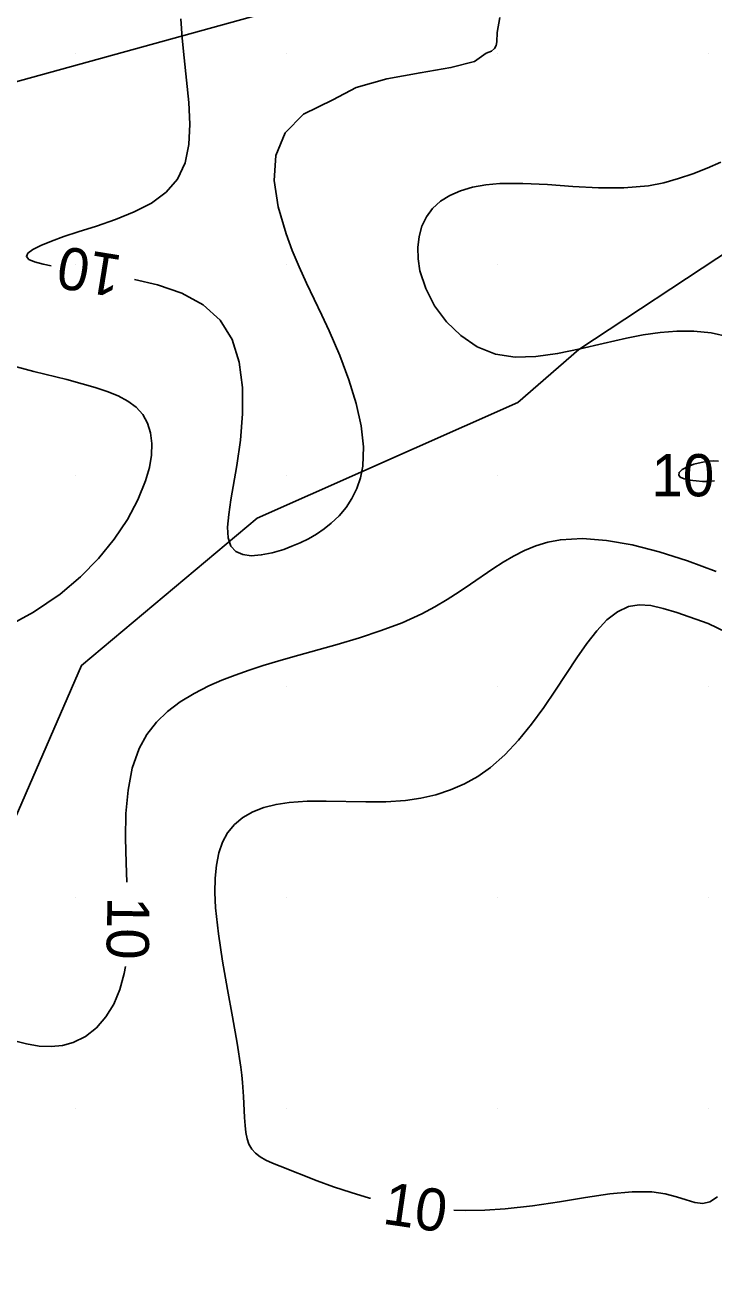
# Model space of a CAD drawing. Extents: x 2602990 to 2605851, y 618069 to 619180.
# Drawn here: x 2603247.6 to 2603280.3, y 618261.9 to 618321.3 of the extents above; entities that cross this region are included whole.
import ezdxf

# ---------------------------------------------------------------- set-up
doc = ezdxf.new("R2010")
doc.units = 0
for name, color, linetype in [('DTM Contours Major', 7, 'Continuous'), ('DTM Contours Major Text', 7, 'Continuous'), ('DTM Contours Minor', 7, 'Continuous'), ('DTM Contours Minor Text', 7, 'Continuous'), ('Exist DTM QL2 LIDAR Elevation Point', 7, 'Continuous'), ('PH Exist DTM Obscure Area', 7, 'Continuous')]:
    doc.layers.add(name, color=color, linetype=linetype)

msp = doc.modelspace()

# ---------------------------------------------------------------- linework, layer by layer
at = {"layer": 'DTM Contours Major'}
for points in [[(2603280.976, 618306.565), (2603280.141, 618306.74), (2603279.32, 618306.823), (2603278.511, 618306.827), (2603277.711, 618306.765), (2603276.916, 618306.651), (2603276.126, 618306.498), (2603275.02, 618306.246), (2603273.928, 618305.988), (2603272.86, 618305.765), (2603271.828, 618305.622), (2603270.844, 618305.601), (2603269.918, 618305.744), (2603269.048, 618306.09), (2603268.266, 618306.613), (2603267.589, 618307.272), (2603267.032, 618308.031), (2603266.609, 618308.848), (2603266.337, 618309.686), (2603266.245, 618310.251), (2603266.229, 618310.798), (2603266.291, 618311.32), (2603266.429, 618311.807), (2603266.644, 618312.251), (2603266.935, 618312.643), (2603267.307, 618312.981), (2603267.75, 618313.26), (2603268.26, 618313.481), (2603268.829, 618313.646), (2603269.451, 618313.759), (2603270.121, 618313.821), (2603271.216, 618313.83), (2603272.378, 618313.771), (2603273.582, 618313.687), (2603274.798, 618313.622), (2603276.001, 618313.618), (2603277.162, 618313.72), (2603277.89, 618313.861), (2603278.592, 618314.054), (2603279.273, 618314.289), (2603279.937, 618314.555), (2603280.588, 618314.84)], [(2603247.219, 618305.132), (2603248.043, 618304.919), (2603249.604, 618304.529), (2603250.331, 618304.338), (2603250.945, 618304.161), (2603251.516, 618303.97), (2603252.036, 618303.756), (2603252.495, 618303.508), (2603252.886, 618303.218), (2603253.199, 618302.876), (2603253.429, 618302.474), (2603253.574, 618302.016), (2603253.635, 618301.507), (2603253.615, 618300.952), (2603253.515, 618300.358), (2603253.336, 618299.729), (2603252.972, 618298.833), (2603252.473, 618297.907), (2603251.848, 618296.974), (2603251.103, 618296.058), (2603250.245, 618295.181), (2603249.281, 618294.368), (2603248.03, 618293.517), (2603246.696, 618292.78)], [(2603252.447, 618280.716), (2603252.409, 618281.629), (2603252.383, 618282.806), (2603252.406, 618283.966), (2603252.504, 618285.079), (2603252.704, 618286.118), (2603253.032, 618287.054), (2603253.398, 618287.711), (2603253.851, 618288.292), (2603254.382, 618288.806), (2603254.979, 618289.259), (2603255.632, 618289.66), (2603256.331, 618290.017), (2603256.944, 618290.285), (2603257.579, 618290.532), (2603258.236, 618290.762), (2603258.912, 618290.977), (2603259.605, 618291.184), (2603260.314, 618291.386), (2603262.42, 618291.976), (2603263.473, 618292.292), (2603264.503, 618292.634), (2603265.491, 618293.011), (2603266.422, 618293.432), (2603267.041, 618293.763), (2603267.629, 618294.113), (2603268.191, 618294.475), (2603268.734, 618294.842), (2603269.788, 618295.562), (2603270.278, 618295.878), (2603270.776, 618296.17), (2603271.289, 618296.431), (2603271.825, 618296.652), (2603272.391, 618296.825), (2603272.995, 618296.942), (2603274.035, 618296.999), (2603275.171, 618296.912), (2603276.389, 618296.697), (2603277.673, 618296.369), (2603279.007, 618295.946), (2603280.375, 618295.442)], [(2603247.067, 618273.212), (2603247.695, 618273.048), (2603248.295, 618272.951), (2603248.867, 618272.927), (2603249.405, 618272.979), (2603249.907, 618273.111), (2603250.491, 618273.399), (2603251.008, 618273.809), (2603251.454, 618274.327), (2603251.824, 618274.939), (2603252.115, 618275.63), (2603252.324, 618276.386), (2603252.38, 618276.725)]]:
    msp.add_lwpolyline(points, dxfattribs=at)
at = {"layer": 'DTM Contours Minor'}
for points in [[(2603269.479, 618320), (2603269.72, 618320.094), (2603269.868, 618320.216), (2603269.947, 618320.366), (2603269.979, 618320.544), (2603270, 618320.984), (2603270.122, 618321.689)], [(2603255.009, 618321.62), (2603255.064, 618320.713), (2603255.156, 618319.782), (2603255.279, 618318.716), (2603255.386, 618317.66), (2603255.437, 618316.639), (2603255.391, 618315.678), (2603255.21, 618314.803), (2603254.853, 618314.037), (2603254.311, 618313.414), (2603253.61, 618312.899), (2603252.795, 618312.474), (2603251.915, 618312.117), (2603251.015, 618311.809), (2603250.142, 618311.529), (2603249.469, 618311.305), (2603248.871, 618311.09), (2603248.371, 618310.885), (2603247.992, 618310.693), (2603247.758, 618310.516), (2603247.693, 618310.357), (2603247.804, 618310.224), (2603248.071, 618310.104), (2603248.478, 618309.995), (2603248.866, 618309.919)], [(2603252.815, 618309.282), (2603253.903, 618309.021), (2603255.046, 618308.62), (2603256.059, 618308.075), (2603256.872, 618307.353), (2603257.437, 618306.431), (2603257.775, 618305.35), (2603257.926, 618304.16), (2603257.929, 618302.914), (2603257.827, 618301.663), (2603257.659, 618300.459), (2603257.38, 618298.836), (2603257.276, 618298.138), (2603257.225, 618297.532), (2603257.251, 618297.03), (2603257.376, 618296.643), (2603257.607, 618296.387), (2603257.936, 618296.239), (2603258.345, 618296.187), (2603258.817, 618296.22), (2603259.336, 618296.324), (2603259.883, 618296.487), (2603260.273, 618296.631), (2603260.665, 618296.799), (2603261.052, 618296.991), (2603261.429, 618297.209), (2603261.791, 618297.453), (2603262.133, 618297.723), (2603262.503, 618298.075), (2603262.832, 618298.466), (2603263.115, 618298.896), (2603263.345, 618299.365), (2603263.518, 618299.874), (2603263.626, 618300.424), (2603263.662, 618301.341), (2603263.552, 618302.338), (2603263.316, 618303.402), (2603262.971, 618304.516), (2603262.537, 618305.667), (2603262.032, 618306.838), (2603261.683, 618307.588), (2603260.964, 618309.101), (2603260.615, 618309.869), (2603260.286, 618310.646), (2603259.989, 618311.434), (2603259.612, 618312.711), (2603259.425, 618313.969), (2603259.509, 618315.158), (2603259.947, 618316.224), (2603260.822, 618317.117), (2603262.215, 618317.785), (2603263.317, 618318.38), (2603264.768, 618318.783), (2603266.34, 618319.071), (2603267.802, 618319.32), (2603268.924, 618319.604), (2603269.479, 618320)], [(2603278.604, 618300), (2603278.615, 618300.131), (2603278.761, 618300.268), (2603279.007, 618300.399), (2603279.318, 618300.517), (2603279.661, 618300.609), (2603280, 618300.667), (2603280.254, 618300.683), (2603280.482, 618300.673)], [(2603280.291, 618299.727), (2603280, 618299.704), (2603279.726, 618299.707), (2603279.418, 618299.73), (2603279.114, 618299.772), (2603278.851, 618299.832), (2603278.669, 618299.908), (2603278.604, 618300)], [(2603280, 618292.977), (2603278.503, 618293.49), (2603277.858, 618293.691), (2603277.27, 618293.822), (2603276.728, 618293.859), (2603276.222, 618293.778), (2603275.697, 618293.533), (2603275.197, 618293.141), (2603274.714, 618292.63), (2603274.244, 618292.024), (2603273.777, 618291.352), (2603272.766, 618289.815), (2603272.207, 618288.993), (2603271.624, 618288.195), (2603271.012, 618287.441), (2603270.365, 618286.751), (2603269.678, 618286.148), (2603269.074, 618285.725), (2603268.441, 618285.371), (2603267.78, 618285.085), (2603267.092, 618284.861), (2603266.38, 618284.696), (2603265.646, 618284.589), (2603264.714, 618284.525), (2603263.766, 618284.515), (2603261.889, 618284.553), (2603260.993, 618284.548), (2603260.146, 618284.494), (2603259.519, 618284.399), (2603258.939, 618284.251), (2603258.414, 618284.047), (2603257.948, 618283.783), (2603257.549, 618283.455), (2603257.222, 618283.059), (2603256.979, 618282.61), (2603256.803, 618282.099), (2603256.689, 618281.528), (2603256.629, 618280.903), (2603256.62, 618280.228), (2603256.654, 618279.506), (2603256.784, 618278.268), (2603256.982, 618276.964), (2603257.217, 618275.636), (2603257.461, 618274.329), (2603257.683, 618273.084), (2603257.854, 618271.944), (2603257.897, 618271.57), (2603257.931, 618271.215), (2603257.979, 618270.558), (2603258.027, 618269.559), (2603258.05, 618269.186), (2603258.087, 618268.851), (2603258.145, 618268.554), (2603258.234, 618268.293), (2603258.363, 618268.067), (2603258.541, 618267.871), (2603258.766, 618267.701), (2603259.038, 618267.547), (2603259.355, 618267.402), (2603259.714, 618267.255), (2603261.463, 618266.569), (2603262.239, 618266.284), (2603263.071, 618266.005), (2603263.953, 618265.747), (2603263.986, 618265.739)], [(2603280.843, 618292.559), (2603280, 618292.977)], [(2603267.936, 618265.166), (2603268.475, 618265.149), (2603269.416, 618265.165), (2603270.368, 618265.227), (2603271.664, 618265.376), (2603272.942, 618265.571), (2603274.176, 618265.773), (2603275.337, 618265.945), (2603276.396, 618266.047), (2603277.326, 618266.042), (2603277.947, 618265.949), (2603278.485, 618265.808), (2603278.955, 618265.658), (2603279.367, 618265.541), (2603279.737, 618265.494), (2603280.077, 618265.56), (2603280.438, 618265.801)]]:
    msp.add_lwpolyline(points, dxfattribs=at)
at = {"layer": 'Exist DTM QL2 LIDAR Elevation Point'}
for p, q in [((2603250, 618320), (2603250, 618320)), ((2603260, 618320), (2603260, 618320)), ((2603270, 618320), (2603270, 618320)), ((2603280, 618320), (2603280, 618320)), ((2603250, 618310), (2603250, 618310)), ((2603260, 618310), (2603260, 618310)), ((2603270, 618310), (2603270, 618310)), ((2603280, 618310), (2603280, 618310)), ((2603250, 618300), (2603250, 618300)), ((2603260, 618300), (2603260, 618300)), ((2603270, 618300), (2603270, 618300)), ((2603280, 618300), (2603280, 618300)), ((2603250, 618290), (2603250, 618290)), ((2603260, 618290), (2603260, 618290)), ((2603270, 618290), (2603270, 618290)), ((2603280, 618290), (2603280, 618290)), ((2603250, 618280), (2603250, 618280)), ((2603260, 618280), (2603260, 618280)), ((2603270, 618280), (2603270, 618280)), ((2603280, 618280), (2603280, 618280)), ((2603250, 618270), (2603250, 618270)), ((2603260, 618270), (2603260, 618270)), ((2603270, 618270), (2603270, 618270)), ((2603280, 618270), (2603280, 618270))]:
    msp.add_line(p, q, dxfattribs=at)
at = {"layer": 'PH Exist DTM Obscure Area'}
for points in [[(2603301.286, 618333.579), (2603234.869, 618315.243), (2603198.873, 618301.136), (2603152.972, 618286.732), (2603122.123, 618276.477)], [(2603214.095, 618205.908), (2603236.88, 618213.413), (2603242.897, 618213.478), (2603249.693, 618219.367), (2603251.965, 618230.407), (2603242.886, 618234.25), (2603237.813, 618233.008), (2603228.59, 618230.749), (2603221.465, 618233.662), (2603224.846, 618242.398), (2603230.879, 618251.696), (2603237.516, 618266.865), (2603238.005, 618272.966), (2603243.908, 618279.156), (2603247.154, 618283.746), (2603250.298, 618290.986), (2603258.623, 618297.971), (2603270.971, 618303.439), (2603273.862, 618305.958), (2603281.14, 618310.76)]]:
    msp.add_lwpolyline(points, dxfattribs=at)

# ---------------------------------------------------------------- texts
at = {"layer": 'DTM Contours Major Text'}
msp.add_text('10', height=2, rotation=269.04293, dxfattribs=at).set_placement((2603251.531, 618280.033))
at = {"layer": 'DTM Contours Minor Text'}
for rotation, p in [(170.83777, (2603252.285, 618310.395)), (351.74515, (2603264.516, 618264.537))]:
    msp.add_text('10', height=2, rotation=rotation, dxfattribs=at).set_placement(p)
msp.add_text('10', height=2, dxfattribs=at).set_placement((2603277.305, 618299))

doc.saveas('drawing.dxf')
